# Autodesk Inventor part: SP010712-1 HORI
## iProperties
Created: 2013-01
Part Number: SP010712-1 HORI
Material: Aluminum-6061
Description: PROFILE 45X45 UL
Document SubType Name: Modeling
Designer: Administrator
Stock Number: 20.1063 PROFILE 45X45 UL
Density: 2.71 g/cm^3
FINISH: CLEAR ANODIZED
Author: Administrator
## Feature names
1. Extrusion1
